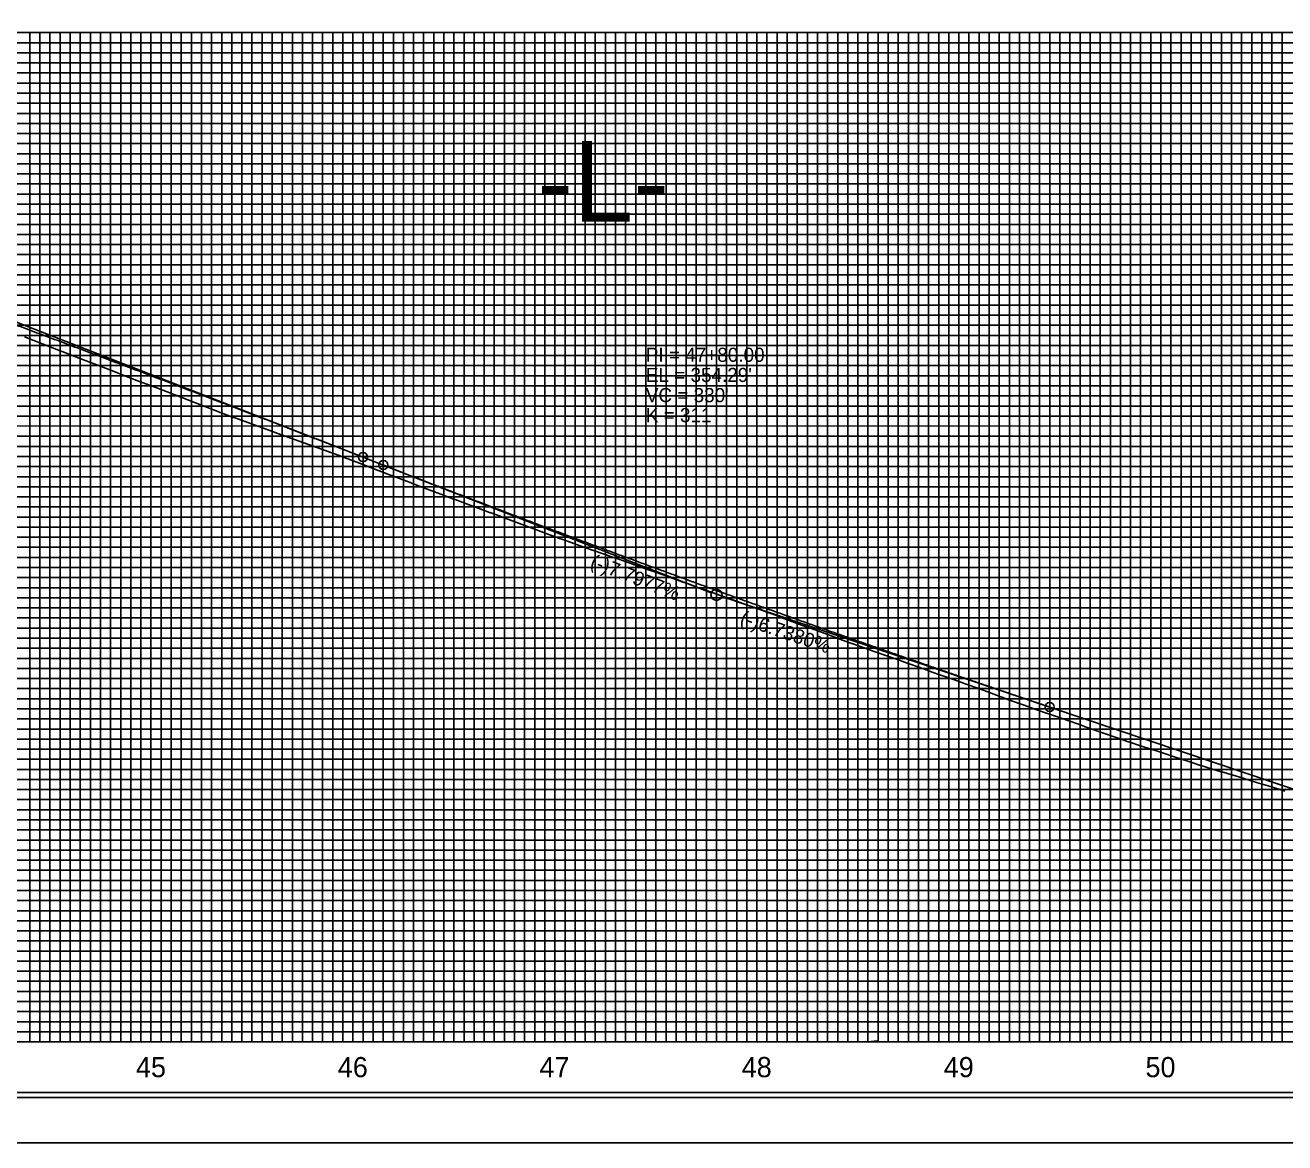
# Model space of a CAD drawing. Extents: x 571503 to 593215, y -77195 to -51828.
# Drawn here: x 582935 to 583558, y -74015 to -73461 of the extents above; entities that cross this region are included whole.
import ezdxf

# ---------------------------------------------------------------- set-up
doc = ezdxf.new("R2010")
doc.units = 0
for name, color, linetype in [('Exist Vertical Profile Ground Line', 7, 'Continuous'), ('Exist Vertical Profile Horizontal Axis Label Major', 7, 'Continuous'), ('Exist Vertical Profile Vertical Axis Label', 7, 'Continuous'), ('Prop Vertical Profile Curve Label', 7, 'Continuous'), ('Prop Vertical Profile Grade', 7, 'Continuous'), ('Prop Vertical Profile Grade Label', 7, 'Continuous'), ('Prop VPI Label', 7, 'Continuous'), ('Sheet Cutting Line CELL', 7, 'Continuous'), ('Sheet DOT Grid CELL', 7, 'Continuous'), ('Sheet Layout Profile Border Port 2', 7, 'Continuous'), ('Sheet Plot Border Inside CELL', 7, 'Continuous'), ('Sheet Plot Border Outside CELL', 7, 'Continuous'), ('Sheet Profile CELL', 7, 'Continuous'), ('Sheet Profile Grid Major CELL', 7, 'Continuous'), ('Sheet Profile Grid Middle CELL', 7, 'Continuous'), ('Sheet Profile Grid Minor CELL', 7, 'Continuous')]:
    doc.layers.add(name, color=color, linetype=linetype)

msp = doc.modelspace()

# ---------------------------------------------------------------- linework, layer by layer
at = {"layer": 'Exist Vertical Profile Ground Line'}
for points in [[(582934.4, -73615.87), (582943.67, -73619.46), (582952.9, -73623.03), (582952.95, -73623.04), (582953.07, -73623.09), (582962.22, -73626.63), (582971.5, -73630.22), (582980.41, -73633.67), (582980.77, -73633.81), (582984.83, -73635.38), (582984.84, -73635.38), (582990.05, -73637.38), (582999.33, -73640.94), (583006.24, -73643.6), (583006.27, -73643.61), (583037.74, -73655.7), (583038.16, -73655.85), (583059.02, -73663.39), (583059.22, -73663.46), (583090.19, -73674.66), (583091.37, -73675.07), (583101.52, -73678.96), (583107.28, -73681.16), (583112.53, -73683.17), (583113.03, -73683.34), (583113.79, -73683.61), (583118.78, -73685.51), (583124.53, -73687.71), (583130.28, -73689.9), (583136.03, -73692.09), (583141.78, -73694.28), (583142.65, -73694.61), (583145.88, -73695.82), (583147.53, -73696.44), (583153.28, -73698.58), (583159.04, -73700.73), (583164.51, -73702.77), (583164.79, -73702.87), (583166.16, -73703.38), (583169.84, -73704.73), (583170.54, -73704.99), (583176.29, -73707.13), (583182.04, -73709.27), (583187.79, -73711.4), (583193.54, -73713.54), (583198.07, -73715.22)], [(583198.07, -73715.22), (583199.29, -73715.67), (583200.44, -73716.08), (583205.05, -73717.72), (583210.8, -73719.77), (583216.55, -73721.81), (583220.42, -73723.18), (583222.3, -73723.81), (583224.53, -73724.55), (583228.05, -73725.8), (583233.8, -73727.84), (583239.55, -73729.88), (583245.3, -73731.92), (583251.05, -73733.96), (583252.35, -73734.42), (583253.16, -73734.71), (583256.81, -73735.96), (583257.34, -73736.14), (583259.96, -73737.13), (583262.56, -73738.06), (583268.31, -73740.11), (583268.69, -73740.25), (583274.06, -73742.18), (583279.81, -73744.25), (583282.71, -73745.29), (583285.56, -73746.31), (583286.11, -73746.5), (583291.31, -73748.37), (583297.06, -73750.44), (583302.82, -73752.5), (583306.77, -73753.92), (583308.57, -73754.61), (583314.32, -73756.8), (583319.05, -73758.61), (583320.07, -73758.97), (583325.82, -73761.04), (583331.57, -73763.1), (583332.86, -73763.57), (583337.32, -73765.27), (583338.01, -73765.53), (583343.07, -73767.35), (583348.83, -73769.42), (583354.58, -73771.49), (583356.56, -73772.2), (583360.33, -73773.53), (583366.08, -73775.56), (583370.07, -73776.97), (583371.83, -73777.6), (583377.58, -73779.65), (583381.27, -73780.97), (583383.33, -73781.7), (583388.08, -73783.37), (583389.08, -73783.73), (583394.83, -73785.78), (583400.59, -73787.83), (583406.33, -73789.89), (583412.09, -73792.01), (583417.84, -73794.14), (583420.02, -73794.94), (583420.42, -73795.08), (583423.59, -73796.26), (583427.88, -73797.84), (583429.34, -73798.35), (583435.09, -73800.36), (583440.84, -73802.38), (583446.23, -73804.26), (583446.6, -73804.39), (583452.35, -73806.41), (583458.1, -73808.42), (583459.59, -73808.95), (583463.85, -73810.44), (583469.6, -73812.46), (583475.35, -73814.48), (583478.12, -73815.45), (583480.88, -73816.42), (583481.1, -73816.49), (583486.85, -73818.36), (583492.6, -73820.24), (583494.33, -73820.8), (583498.36, -73822.11), (583504.11, -73824), (583509.86, -73825.88), (583512.86, -73826.86), (583515.61, -73827.76), (583518.5, -73828.7), (583521.36, -73829.58), (583526.32, -73831.09), (583527.11, -73831.33), (583532.86, -73833.04), (583537.19, -73834.33), (583538.61, -73834.76), (583544.37, -73836.52), (583550.12, -73838.29), (583555.87, -73840.05), (583558.44, -73840.84)]]:
    msp.add_lwpolyline(points, dxfattribs=at)
at = {"layer": 'Prop Vertical Profile Curve Label'}
for centre in [(583101.98, -73675.41), (583111.98, -73679.31), (583441.98, -73799.23)]:
    msp.add_circle(centre, 2.25, dxfattribs=at)
at = {"layer": 'Prop Vertical Profile Grade'}
for p, q in [((583101.98, -73675.41), (583111.98, -73679.31)), ((583441.98, -73799.23), (583571.98, -73843.03))]:
    msp.add_line(p, q, dxfattribs=at)
for points in [[(582596.98, -73491.67), (582607.08, -73495.09), (582617.18, -73498.52), (582627.28, -73501.96), (582637.38, -73505.41), (582647.48, -73508.86), (582657.58, -73512.33), (582667.68, -73515.81), (582677.78, -73519.3), (582687.88, -73522.81), (582697.98, -73526.32), (582708.08, -73529.84), (582718.18, -73533.37), (582728.28, -73536.92), (582738.38, -73540.47), (582748.48, -73544.03), (582758.58, -73547.61), (582768.68, -73551.19), (582778.78, -73554.79), (582788.88, -73558.4), (582798.98, -73562.01), (582809.08, -73565.64), (582819.18, -73569.28), (582829.28, -73572.93), (582839.38, -73576.59), (582849.48, -73580.26), (582859.58, -73583.94), (582869.68, -73587.63), (582879.78, -73591.33), (582889.88, -73595.04), (582899.98, -73598.76), (582910.08, -73602.49), (582920.18, -73606.24), (582930.28, -73609.99), (582940.38, -73613.76), (582950.48, -73617.53), (582960.58, -73621.32), (582970.68, -73625.11), (582980.78, -73628.92), (582990.88, -73632.73), (583000.98, -73636.56), (583011.08, -73640.4), (583021.18, -73644.25), (583031.28, -73648.11), (583041.38, -73651.98), (583051.48, -73655.86), (583061.58, -73659.75), (583071.68, -73663.65), (583081.78, -73667.56), (583091.88, -73671.48), (583101.98, -73675.41)], [(583111.98, -73679.31), (583118.58, -73681.88), (583125.18, -73684.45), (583131.78, -73687), (583138.38, -73689.55), (583144.98, -73692.09), (583151.58, -73694.63), (583158.18, -73697.15), (583164.78, -73699.68), (583171.38, -73702.19), (583177.98, -73704.7), (583184.58, -73707.2), (583191.18, -73709.69), (583197.78, -73712.17), (583204.38, -73714.65), (583210.98, -73717.13), (583217.58, -73719.59), (583224.18, -73722.05), (583230.78, -73724.5), (583237.38, -73726.94), (583243.98, -73729.38), (583250.58, -73731.81), (583257.18, -73734.23), (583263.78, -73736.65), (583270.38, -73739.06), (583276.98, -73741.46), (583283.58, -73743.85), (583290.18, -73746.24), (583296.78, -73748.62), (583303.38, -73751), (583309.98, -73753.36), (583316.58, -73755.72), (583323.18, -73758.08), (583329.78, -73760.42), (583336.38, -73762.76), (583342.98, -73765.09), (583349.58, -73767.42), (583356.18, -73769.74), (583362.78, -73772.05), (583369.38, -73774.35), (583375.98, -73776.65), (583382.58, -73778.94), (583389.18, -73781.22), (583395.78, -73783.5), (583402.38, -73785.77), (583408.98, -73788.03), (583415.58, -73790.28), (583422.18, -73792.53), (583428.78, -73794.77), (583435.38, -73797.01), (583441.98, -73799.23)]]:
    msp.add_spline(points, degree=3, dxfattribs=at)
at = {"layer": 'Prop VPI Label'}
for p, q in [((583101.98, -73675.41), (582839.55, -73573.09)), ((583111.98, -73679.31), (583274.42, -73742.65)), ((583441.98, -73799.23), (583279.59, -73744.52))]:
    msp.add_line(p, q, dxfattribs=at)
msp.add_circle((583276.98, -73743.64), 2.75, dxfattribs=at)
at = {"layer": 'Sheet Cutting Line CELL'}
msp.add_line((582329.98, -74015.09), (584013.98, -74015.09), dxfattribs=at)
at = {"layer": 'Sheet DOT Grid CELL'}
for p, q in [((582496.98, -73465.09), (583996.87, -73465.09)), ((582946.98, -73465.09), (582946.98, -73965.09)), ((582996.98, -73465.09), (582996.98, -73965.09)), ((583046.98, -73465.09), (583046.98, -73965.09)), ((583096.98, -73465.09), (583096.98, -73965.09)), ((583146.98, -73465.09), (583146.98, -73965.09)), ((583196.98, -73465.09), (583196.98, -73965.09)), ((583246.98, -73465.09), (583246.98, -73965.09)), ((583296.98, -73465.09), (583296.98, -73965.09)), ((583346.98, -73465.09), (583346.98, -73965.09)), ((583396.98, -73465.09), (583396.98, -73965.09)), ((583446.98, -73465.09), (583446.98, -73965.09)), ((583496.98, -73465.09), (583496.98, -73965.09)), ((583546.98, -73465.09), (583546.98, -73965.09)), ((582496.98, -73515.09), (583996.87, -73515.09)), ((582496.98, -73565.09), (583996.87, -73565.09)), ((582496.98, -73615.09), (583996.87, -73615.09)), ((582496.98, -73665.09), (583996.87, -73665.09)), ((582496.98, -73715.09), (583996.87, -73715.09)), ((582496.98, -73765.09), (583996.87, -73765.09)), ((582496.98, -73815.09), (583996.87, -73815.09)), ((582496.98, -73865.09), (583996.87, -73865.09)), ((582496.98, -73915.09), (583996.87, -73915.09))]:
    msp.add_line(p, q, dxfattribs=at)
at = {"layer": 'Sheet Layout Profile Border Port 2'}
msp.add_lwpolyline([(582546.98, -73465.09), (583946.98, -73465.09), (583946.98, -73965.09), (582546.98, -73965.09)], close=True, dxfattribs=at)
at = {"layer": 'Sheet Plot Border Inside CELL'}
msp.add_lwpolyline([(582342.98, -73992.64), (584009.48, -73992.64), (584009.48, -72937.54), (582342.98, -72937.54)], close=True, dxfattribs=at)
at = {"layer": 'Sheet Plot Border Outside CELL'}
msp.add_lwpolyline([(582329.98, -74015.09), (584013.98, -74015.09), (584013.98, -72915.09), (582329.98, -72915.09)], close=True, dxfattribs=at)
at = {"layer": 'Sheet Profile CELL'}
for p, q in [((582496.98, -73465.09), (583996.98, -73465.09)), ((583996.98, -73965.09), (582496.98, -73965.09)), ((582496.98, -73990.09), (583996.98, -73990.09))]:
    msp.add_line(p, q, dxfattribs=at)
msp.add_lwpolyline([(583996.98, -72940.09), (582496.98, -72940.09), (582496.98, -73990.09), (583996.98, -73990.09)], close=True, dxfattribs=at)
at = {"layer": 'Sheet Profile Grid Major CELL'}
for p, q in [((582996.98, -73465.09), (583046.98, -73465.09)), ((583096.98, -73465.09), (583146.98, -73465.09)), ((583196.98, -73465.09), (583246.98, -73465.09)), ((583296.98, -73465.09), (583346.98, -73465.09)), ((583396.98, -73465.09), (583446.98, -73465.09)), ((583496.98, -73465.09), (583546.98, -73465.09))]:
    msp.add_line(p, q, dxfattribs=at)
for points in [[(582896.98, -73465.09), (582946.98, -73465.09), (582946.98, -73965.09), (582996.98, -73965.09), (582996.98, -73465.09), (583046.98, -73465.09), (583046.98, -73965.09), (583096.98, -73965.09), (583096.98, -73465.09), (583146.98, -73465.09), (583146.98, -73965.09), (583196.98, -73965.09), (583196.98, -73465.09), (583246.98, -73465.09), (583246.98, -73965.09), (583296.98, -73965.09), (583296.98, -73465.09), (583346.98, -73465.09), (583346.98, -73965.09), (583396.98, -73965.09), (583396.98, -73465.09), (583446.98, -73465.09), (583446.98, -73965.09), (583496.98, -73965.09), (583496.98, -73465.09), (583546.98, -73465.09), (583546.98, -73965.09), (583596.98, -73965.09)], [(583996.98, -73515.09), (582496.98, -73515.09)], [(583996.98, -73565.09), (582496.98, -73565.09), (582496.98, -73615.09), (583996.98, -73615.09)], [(583996.98, -73665.09), (582496.98, -73665.09), (582496.98, -73715.09), (583996.98, -73715.09)], [(583996.98, -73765.09), (582496.98, -73765.09), (582496.98, -73815.09), (583996.98, -73815.09)], [(583996.98, -73865.09), (582496.98, -73865.09), (582496.98, -73865.09), (582496.98, -73915.09), (583996.98, -73915.09)], [(583996.98, -73965.09), (582496.98, -73965.09)]]:
    msp.add_lwpolyline(points, dxfattribs=at)
at = {"layer": 'Sheet Profile Grid Middle CELL'}
for points in [[(582921.98, -73465.09), (582971.98, -73465.09), (582971.98, -73965.09), (583021.98, -73965.09), (583021.98, -73465.09), (583071.98, -73465.09), (583071.98, -73965.09), (583121.98, -73965.09), (583121.98, -73965.09), (583121.98, -73465.09), (583171.98, -73465.09), (583171.98, -73965.09), (583221.98, -73965.09), (583221.98, -73465.09), (583271.98, -73465.09), (583271.98, -73965.09), (583321.98, -73965.09), (583321.98, -73465.09), (583371.98, -73465.09), (583371.98, -73965.09), (583421.98, -73965.09), (583421.98, -73465.09), (583471.98, -73465.09), (583471.98, -73965.09), (583521.98, -73965.09), (583521.98, -73465.09), (583571.98, -73465.09)], [(582496.98, -73490.09), (583996.98, -73490.09)], [(583996.98, -73540.09), (582496.98, -73540.09), (582496.98, -73590.09), (583996.98, -73590.09)], [(583996.98, -73640.09), (582496.98, -73640.09), (582496.98, -73690.09), (583996.98, -73690.09)], [(583996.98, -73740.09), (582496.98, -73740.09), (582496.98, -73790.09), (583996.98, -73790.09)], [(583996.98, -73840.09), (582496.98, -73840.09), (582496.98, -73890.09), (583996.98, -73890.09)], [(583996.98, -73940.09), (582496.98, -73940.09)]]:
    msp.add_lwpolyline(points, dxfattribs=at)
at = {"layer": 'Sheet Profile Grid Minor CELL'}
for p, q in [((582546.98, -73470.09), (583946.98, -73470.09)), ((583946.98, -73475.09), (582546.98, -73475.09)), ((582546.98, -73480.09), (583946.98, -73480.09)), ((583946.98, -73485.09), (582546.98, -73485.09)), ((582546.98, -73495.09), (583946.98, -73495.09)), ((583946.98, -73500.09), (582546.98, -73500.09)), ((582546.98, -73505.09), (583946.98, -73505.09)), ((583946.98, -73510.09), (582546.98, -73510.09)), ((582546.98, -73520.09), (583946.98, -73520.09)), ((583946.98, -73525.09), (582546.98, -73525.09)), ((582546.98, -73530.09), (583946.98, -73530.09)), ((583946.98, -73535.09), (582546.98, -73535.09)), ((582546.98, -73545.09), (583946.98, -73545.09)), ((583946.98, -73550.09), (582546.98, -73550.09)), ((582546.98, -73555.09), (583946.98, -73555.09)), ((583946.98, -73560.09), (582546.98, -73560.09)), ((582546.98, -73570.09), (583946.98, -73570.09)), ((583946.98, -73575.09), (582546.98, -73575.09)), ((582546.98, -73580.09), (583946.98, -73580.09)), ((583946.98, -73585.09), (582546.98, -73585.09)), ((582546.98, -73595.09), (583946.98, -73595.09)), ((583946.98, -73600.09), (582546.98, -73600.09)), ((582546.98, -73605.09), (583946.98, -73605.09)), ((583946.98, -73610.09), (582546.98, -73610.09)), ((582546.98, -73620.09), (583946.98, -73620.09)), ((583946.98, -73625.09), (582546.98, -73625.09)), ((582546.98, -73630.09), (583946.98, -73630.09)), ((583946.98, -73635.09), (582546.98, -73635.09)), ((582546.98, -73645.09), (583946.98, -73645.09)), ((583946.98, -73650.09), (582546.98, -73650.09)), ((582546.98, -73655.09), (583946.98, -73655.09)), ((583946.98, -73660.09), (582546.98, -73659.94)), ((582546.98, -73670.09), (583946.98, -73670.09)), ((583946.98, -73675.09), (582546.98, -73675.09)), ((582546.98, -73680.09), (583946.98, -73680.09)), ((583946.98, -73685.09), (582546.98, -73685.09)), ((582546.98, -73695.09), (583946.98, -73695.09)), ((583946.98, -73700.09), (582546.98, -73700.09)), ((582546.98, -73705.09), (583946.98, -73705.09)), ((583946.98, -73710.09), (582546.98, -73710.09)), ((582546.98, -73720.09), (583946.98, -73720.09)), ((583946.98, -73725.09), (582546.98, -73725.09)), ((582546.98, -73730.09), (583946.98, -73730.09)), ((583946.98, -73735.09), (582546.98, -73735.09)), ((582546.98, -73745.09), (583946.98, -73745.09)), ((583946.98, -73750.09), (582546.98, -73750.09)), ((582546.98, -73755.09), (583946.98, -73755.09)), ((583946.98, -73760.09), (582546.98, -73760.09)), ((582546.98, -73770.09), (583946.98, -73770.09)), ((583946.98, -73775.09), (582546.98, -73775.09)), ((582546.98, -73780.09), (583946.98, -73780.09)), ((583946.98, -73785.09), (582546.98, -73785.09)), ((582546.98, -73795.09), (583946.98, -73795.09)), ((583946.98, -73800.09), (582546.98, -73800.09)), ((582546.98, -73805.09), (583946.98, -73805.09)), ((583946.98, -73810.09), (582546.98, -73810.09)), ((582546.98, -73820.09), (583946.98, -73820.09)), ((583946.98, -73825.09), (582546.98, -73825.09)), ((582546.98, -73830.09), (583946.98, -73830.09)), ((583946.98, -73835.09), (582546.98, -73835.09)), ((582546.98, -73845.09), (583946.98, -73845.09)), ((583946.98, -73850.09), (582546.98, -73850.09)), ((582546.98, -73855.09), (583946.98, -73855.09)), ((583946.98, -73860.09), (582546.98, -73860.09)), ((582546.98, -73870.09), (583946.98, -73870.09)), ((583946.98, -73875.09), (582546.98, -73875.09)), ((582546.98, -73880.09), (583946.98, -73880.09)), ((583946.98, -73885.09), (582546.98, -73885.09)), ((582546.98, -73895.09), (583946.98, -73895.09)), ((583946.98, -73900.09), (582546.98, -73900.09)), ((582546.98, -73905.09), (583946.98, -73905.09)), ((583946.98, -73910.09), (582546.98, -73910.09)), ((582546.98, -73920.09), (583946.98, -73920.09)), ((583946.98, -73925.09), (582546.98, -73925.09)), ((582546.98, -73930.09), (583946.98, -73930.09)), ((583946.98, -73935.09), (582546.98, -73935.09)), ((582546.98, -73945.09), (583946.98, -73945.09)), ((583946.98, -73950.09), (582546.98, -73950.09)), ((582546.98, -73955.09), (583946.98, -73955.09)), ((582546.98, -73960.09), (583946.98, -73960.09))]:
    msp.add_line(p, q, dxfattribs=at)
for points in [[(582931.98, -73465.09), (582936.98, -73465.09), (582936.98, -73965.09), (582941.98, -73965.09), (582941.98, -73465.09), (582951.98, -73465.09), (582951.98, -73965.09), (582956.98, -73965.09), (582956.98, -73465.09), (582961.98, -73465.09), (582961.98, -73965.09), (582966.98, -73965.09), (582966.98, -73465.09), (582976.98, -73465.09), (582976.98, -73965.09), (582981.98, -73965.09), (582981.98, -73465.09), (582986.98, -73465.09), (582986.98, -73965.09), (582991.98, -73965.09), (582991.98, -73465.09), (583001.98, -73465.09), (583001.98, -73965.09), (583006.98, -73965.09), (583006.98, -73465.09), (583011.98, -73465.09), (583011.98, -73965.09), (583016.98, -73965.09), (583016.98, -73465.09), (583026.98, -73465.09), (583026.98, -73965.09), (583031.98, -73965.09), (583031.98, -73465.09), (583036.98, -73465.09), (583036.98, -73965.09), (583041.98, -73965.09), (583041.98, -73465.09), (583051.98, -73465.09), (583051.98, -73965.09), (583056.98, -73965.09), (583056.98, -73465.09), (583061.98, -73465.09), (583061.98, -73965.09), (583066.98, -73965.09), (583066.98, -73465.09), (583076.98, -73465.09)], [(583076.98, -73465.09), (583076.98, -73965.09), (583081.98, -73965.09), (583081.98, -73465.09), (583086.98, -73465.09), (583086.98, -73965.09), (583091.98, -73965.09), (583091.98, -73465.09), (583101.98, -73465.09), (583101.98, -73965.09), (583106.98, -73965.09), (583106.98, -73465.09), (583111.98, -73465.09), (583111.98, -73965.09), (583116.98, -73965.09), (583116.98, -73465.09), (583126.98, -73465.09), (583126.98, -73965.09), (583131.98, -73965.09), (583131.98, -73465.09), (583136.98, -73465.09), (583136.98, -73965.09), (583141.98, -73965.09), (583141.98, -73465.09), (583151.98, -73465.09), (583151.98, -73965.09), (583156.98, -73965.09), (583156.98, -73465.09), (583161.98, -73465.09), (583161.98, -73965.09), (583166.98, -73965.09), (583166.98, -73465.09), (583176.98, -73465.09), (583176.98, -73965.09), (583181.98, -73965.09), (583181.98, -73465.09), (583186.98, -73465.09), (583186.98, -73965.09), (583191.98, -73965.09), (583191.98, -73465.09), (583201.98, -73465.09), (583201.98, -73965.09), (583201.98, -73965.09), (583206.98, -73965.09), (583206.98, -73465.09), (583211.98, -73465.09), (583211.98, -73965.09), (583216.98, -73965.09), (583216.98, -73465.09), (583226.98, -73465.09), (583226.98, -73965.09), (583231.98, -73965.09), (583231.98, -73465.09), (583236.98, -73465.09), (583236.98, -73965.09), (583241.98, -73965.09), (583241.98, -73465.09), (583251.98, -73465.09), (583251.98, -73965.09), (583256.98, -73965.09), (583256.98, -73465.09), (583261.98, -73465.09), (583261.98, -73965.09), (583266.98, -73965.09), (583266.98, -73465.09), (583276.98, -73465.09), (583276.98, -73965.09), (583281.98, -73965.09), (583281.98, -73465.09), (583286.98, -73465.09), (583286.98, -73965.09), (583291.98, -73965.09), (583291.98, -73465.09), (583301.98, -73465.09), (583301.98, -73965.09), (583306.98, -73965.09), (583306.98, -73465.09), (583311.98, -73465.09), (583311.98, -73965.09), (583316.98, -73965.09), (583316.98, -73465.09), (583326.98, -73465.09), (583326.98, -73965.09), (583331.98, -73965.09), (583331.98, -73465.09), (583336.98, -73465.09), (583336.98, -73965.09), (583341.98, -73965.09), (583341.98, -73465.09), (583351.98, -73465.09), (583351.98, -73965.09), (583356.68, -73964.54), (583356.98, -73965.09), (583356.98, -73465.09), (583361.98, -73465.09), (583361.98, -73965.09), (583366.98, -73965.09), (583366.98, -73465.09), (583376.98, -73465.09), (583376.98, -73965.09), (583381.98, -73965.09)], [(583381.98, -73965.09), (583381.98, -73465.09), (583386.98, -73465.09), (583386.98, -73965.09), (583391.98, -73965.09), (583391.98, -73465.09), (583401.98, -73465.09), (583401.98, -73965.09), (583406.98, -73965.09), (583406.98, -73465.09), (583411.98, -73465.09), (583411.98, -73965.09), (583416.98, -73965.09), (583416.98, -73465.09), (583426.98, -73465.09), (583426.98, -73965.09), (583431.98, -73965.09), (583431.98, -73465.09), (583436.98, -73465.09), (583436.98, -73965.09), (583441.98, -73965.09), (583441.98, -73465.09), (583451.98, -73465.09), (583451.98, -73965.09), (583456.98, -73965.09), (583456.98, -73465.09), (583461.98, -73465.09), (583461.98, -73965.09), (583466.98, -73965.09), (583466.98, -73465.09), (583476.98, -73465.09), (583476.98, -73965.09), (583481.98, -73965.09), (583481.98, -73465.09), (583486.98, -73465.09), (583486.98, -73965.09), (583491.98, -73965.09), (583491.98, -73465.09), (583501.98, -73465.09), (583501.98, -73965.09), (583506.98, -73965.09), (583506.98, -73465.09), (583511.98, -73465.09), (583511.98, -73965.09), (583516.98, -73965.09), (583516.98, -73465.09), (583526.98, -73465.09), (583526.98, -73965.09), (583531.98, -73965.09), (583531.98, -73465.09), (583536.98, -73465.09), (583536.98, -73965.09), (583541.98, -73965.09), (583541.98, -73465.09), (583551.98, -73465.09), (583551.98, -73965.09), (583556.98, -73965.09), (583556.98, -73465.09), (583561.98, -73465.09)]]:
    msp.add_lwpolyline(points, dxfattribs=at)

# ---------------------------------------------------------------- texts
at = {"layer": 'Exist Vertical Profile Horizontal Axis Label Major'}
for s, p in [('45', (582989.53, -73982.59)), ('46', (583089.47, -73982.59)), ('47', (583189.33, -73982.59)), ('48', (583289.45, -73982.59)), ('49', (583389.49, -73982.59)), ('50', (583489.37, -73982.59))]:
    msp.add_text(s, height=10, dxfattribs=at).set_placement(p)
at = {"layer": 'Exist Vertical Profile Vertical Axis Label'}
msp.add_text('-L-', height=40, dxfattribs=at).set_placement((583188.23, -73558.74))
at = {"layer": 'Prop Vertical Profile Curve Label'}
for s, p in [("VC = 330'", (583241.98, -73648.19)), ('K = 311', (583241.98, -73658.1))]:
    msp.add_text(s, height=7, dxfattribs=at).set_placement(p)
at = {"layer": 'Prop Vertical Profile Grade Label'}
for s, rotation, p in [('(-)7.7977%', 338.69987, (583213.95, -73729.8)), ('(-)6.7380%', 341.38133, (583288.14, -73757.96))]:
    msp.add_text(s, height=7, rotation=rotation, dxfattribs=at).set_placement(p)
at = {"layer": 'Prop VPI Label'}
for s, p in [('PI = 47+80.00', (583241.98, -73628.19)), ("EL = 354.29'", (583241.98, -73638.19))]:
    msp.add_text(s, height=7, dxfattribs=at).set_placement(p)

doc.saveas('drawing.dxf')
